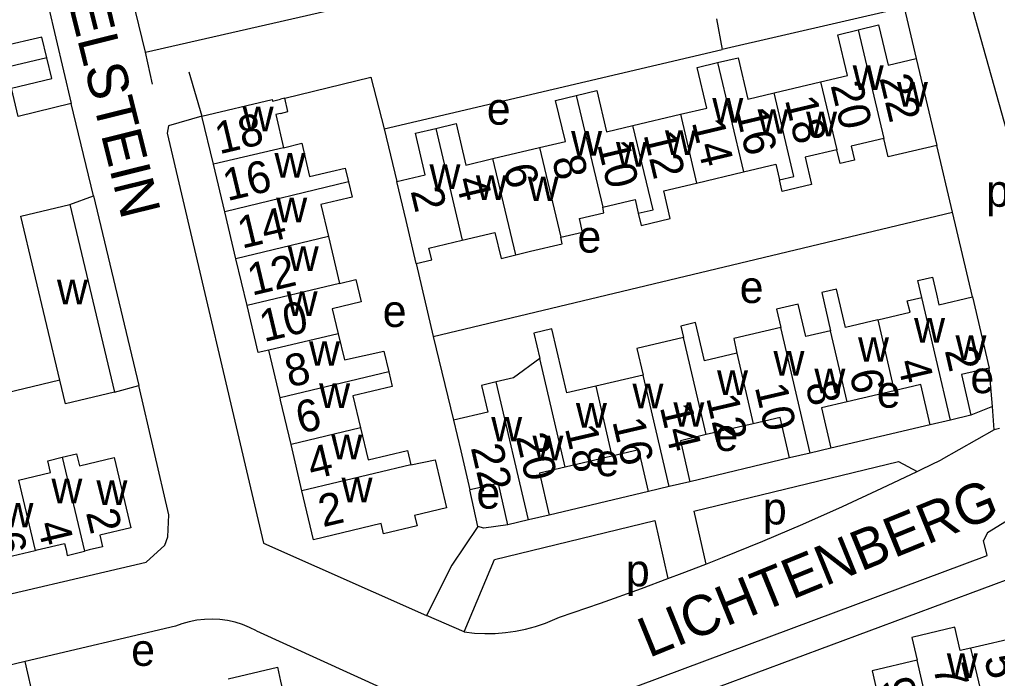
# Model space of a CAD drawing. Extents: x 157646 to 159241, y 379213 to 381217.
# Drawn here: x 158967.4 to 159089.5, y 380734 to 380816.2 of the extents above; entities that cross this region are included whole.
import ezdxf

# ---------------------------------------------------------------- set-up
doc = ezdxf.new("R2010")
doc.units = 0
for name, color, linetype in [('BLT_Basislijn', 7, 'Continuous'), ('BLT_Bebouwing', 7, 'Continuous'), ('BLT_Centroide', 7, 'Continuous'), ('BLT_Huisnummer', 7, 'Continuous'), ('BLT_Huisnummer_ tussenligend', 7, 'Continuous'), ('BLT_Onderverdeling_panden', 7, 'Continuous'), ('BLT_Straatnaam', 7, 'Continuous')]:
    doc.layers.add(name, color=color, linetype=linetype)

msp = doc.modelspace()

# ---------------------------------------------------------------- linework, layer by layer
at = {"layer": 'BLT_Basislijn'}
for p, q in [((158983.11, 380812.15), (158977.53, 380835.61)), ((158983.11, 380812.15), (159034.87, 380824)), ((159077.86, 380817.75), (159079.36, 380811.37)), ((159054.42, 380816.35), (159055.16, 380812.49)), ((158984, 380808.18), (158983.11, 380812.15)), ((159012.95, 380802.61), (159055.16, 380812.49)), ((158973.83, 380805.75), (158967.23, 380804.14)), ((158976.62, 380794.22), (158973.83, 380805.75)), ((159012.95, 380802.61), (159014.5, 380796)), ((159083.91, 380792.17), (159081.95, 380800.52)), ((158973.68, 380793.14), (158976.62, 380794.22)), ((158976.62, 380794.22), (158982.31, 380770.52)), ((159019.06, 380776.66), (159083.91, 380792.17)), ((159086.41, 380781.6), (159083.91, 380792.17)), ((159016.94, 380785.76), (159019.06, 380776.66)), ((159019.06, 380776.66), (159021.61, 380766.21)), ((159088.89, 380767.92), (159088.48, 380772.7)), ((158972.42, 380771.22), (158961.87, 380768.65)), ((158979.25, 380769.69), (158982.31, 380770.52)), ((159088.89, 380767.92), (159086.19, 380766.82)), ((159089.11, 380764.99), (159088.89, 380767.92)), ((159081.12, 380765.64), (159068.72, 380762.7)), ((159089.11, 380764.99), (159082.49, 380761.27)), ((159089.77, 380765.17), (159089.11, 380764.99)), ((159063.55, 380761.5), (159051.11, 380758.53)), ((159024.61, 380752.92), (159023.64, 380757.49)), ((159045.93, 380757.32), (159033.55, 380754.35)), ((159051.59, 380754.84), (159053.09, 380748.24)), ((159046.73, 380753.67), (159048.37, 380746.43)), ((159035.86, 380725.94), (159107.8, 380752.64)), ((159022.93, 380739.77), (159018.2, 380741.8)), ((158986.88, 380740.47), (158968.1, 380736.07)), ((158996.99, 380739.89), (159012.87, 380732.66)), ((158968.1, 380736.07), (158959.72, 380734.11)), ((158969.87, 380728.34), (158968.1, 380736.07))]:
    msp.add_line(p, q, dxfattribs=at)
for points in [[(158950.45, 380874.83), (158953.9, 380875.15), (158955.51, 380874.99), (158957.69, 380873.05), (158958.48, 380871.06), (158973.83, 380805.75)], [(159085.81, 380819.61), (159092.6, 380795.38), (159096.65, 380780.35)], [(159077.86, 380817.75), (159077.39, 380817.64), (159055.16, 380812.49)], [(158988.55, 380809.71), (158990.18, 380804.18)], [(159000.52, 380806.43), (159011.27, 380809.03), (159012.95, 380802.61)], [(158990.18, 380804.18), (158985.98, 380802.97), (158985.82, 380802.07), (158997.85, 380750.84), (159018.2, 380741.8)], [(158934.65, 380738.13), (158934.9, 380737.3), (158935.48, 380737.32), (158983.21, 380748.46), (158985.53, 380750.59), (158985.91, 380751.64), (158986.02, 380754.38), (158982.31, 380770.52)], [(159051.59, 380754.84), (159077.17, 380761.03), (159079.5, 380759.81)], [(159079.5, 380759.81), (159079.98, 380760.04), (159082.49, 380761.27)], [(159053.09, 380748.24), (159055.2, 380749.07), (159060.22, 380751.11), (159065.21, 380753.24), (159070.17, 380755.43), (159075.09, 380757.7), (159079.5, 380759.81)], [(159094.81, 380755.74), (159091.19, 380753.93), (159088.28, 380752.14), (159087.76, 380751.2)], [(159022.93, 380739.77), (159026.72, 380748.83), (159046.73, 380753.67)], [(159024.61, 380752.92), (159021.37, 380748.1), (159018.2, 380741.8)], [(159028.39, 380753.15), (159025.37, 380752.73), (159024.61, 380752.92)], [(159035.62, 380732.02), (159039.36, 380731.08), (159088.22, 380749.33), (159087.76, 380751.2)], [(159048.37, 380746.43), (159050.15, 380747.09), (159053.09, 380748.24)], [(159034.83, 380741.62), (159039.96, 380743.37), (159045.07, 380745.19), (159048.37, 380746.43)], [(158996.99, 380739.89), (158996.12, 380740.32), (158995.23, 380740.68), (158994.31, 380740.97), (158993.37, 380741.18), (158992.42, 380741.3), (158991.46, 380741.36), (158990.49, 380741.33), (158989.54, 380741.22), (158988.59, 380741.03), (158987.67, 380740.76), (158986.88, 380740.47)], [(159022.93, 380739.77), (159024.21, 380739.62), (159025.5, 380739.57), (159026.78, 380739.58), (159028.07, 380739.68), (159029.34, 380739.86), (159030.6, 380740.12), (159031.85, 380740.46), (159033.06, 380740.87), (159034.26, 380741.36), (159034.83, 380741.62)]]:
    msp.add_lwpolyline(points, dxfattribs=at)
at = {"layer": 'BLT_Bebouwing'}
for p, q in [((159079.36, 380811.37), (159081.95, 380800.52)), ((159061.64, 380807.09), (159067.44, 380808.47)), ((159000.52, 380806.43), (159000, 380806.3)), ((158999.99, 380804.52), (158999.4, 380804.38)), ((158999.4, 380804.38), (159000.38, 380800.24)), ((159043.98, 380802.99), (159049.93, 380804.41)), ((159026.52, 380798.87), (159032.32, 380800.25)), ((158993.03, 380792.21), (158991.61, 380798.16)), ((159051.93, 380795.82), (159057.81, 380797.22)), ((158973.68, 380793.14), (158979.25, 380769.69)), ((158994.42, 380786.37), (158993.03, 380792.21)), ((158995.81, 380780.54), (158994.42, 380786.37)), ((159086.41, 380781.6), (159088.48, 380772.7)), ((159007.18, 380777), (159007.96, 380773.73)), ((158999.93, 380769.02), (158998.52, 380774.94)), ((159045.26, 380771.82), (159039.35, 380770.45)), ((159076.63, 380769.89), (159070.75, 380768.52)), ((159000, 380768.7), (158999.93, 380769.02)), ((159001.3, 380763.19), (159000, 380768.7)), ((159059.01, 380765.76), (159053.14, 380764.4)), ((159083.65, 380766.23), (159081.12, 380765.64)), ((159086.19, 380766.82), (159083.65, 380766.23)), ((159002.67, 380757.39), (159001.3, 380763.19)), ((159066.13, 380762.1), (159063.55, 380761.5)), ((159068.72, 380762.7), (159066.13, 380762.1)), ((159041.38, 380761.72), (159035.53, 380760.36)), ((159051.11, 380758.53), (159048.52, 380757.93)), ((159048.52, 380757.93), (159045.93, 380757.32)), ((159030.97, 380753.75), (159028.39, 380753.15)), ((159033.55, 380754.35), (159030.97, 380753.75)), ((159092.8, 380739.29), (159086.2, 380737.74))]:
    msp.add_line(p, q, dxfattribs=at)
for points in [[(158970.81, 380811.46), (158970.2, 380814.05), (158965.13, 380812.86), (158964.36, 380816.13)], [(159067.44, 380808.47), (159070.79, 380809.27), (159069.58, 380814.35), (159072.12, 380814.96)], [(159072.12, 380814.96), (159074.67, 380815.56), (159075.86, 380810.54), (159079.36, 380811.37)], [(158967.23, 380804.14), (158966.4, 380807.68), (158971.42, 380808.86), (158970.81, 380811.46)], [(159049.93, 380804.41), (159053.22, 380805.19), (159052.01, 380810.25), (159054.57, 380810.86)], [(159054.57, 380810.86), (159057.13, 380811.47), (159058.36, 380806.31), (159061.64, 380807.09)], [(159036.91, 380806.75), (159039.48, 380807.36), (159040.7, 380802.21), (159043.98, 380802.99)], [(158990.18, 380804.18), (158998.94, 380806.26), (158998.99, 380806.06), (159000, 380806.3)], [(158999.99, 380804.52), (159000.91, 380804.74), (159000.52, 380806.43)], [(159032.32, 380800.25), (159035.56, 380801.02), (159034.34, 380806.14), (159036.91, 380806.75)], [(158991.61, 380798.16), (158990.18, 380804.18)], [(159014.5, 380796), (159018.07, 380796.85), (159016.83, 380802.05), (159019.37, 380802.65)], [(159019.37, 380802.65), (159021.91, 380803.25), (159023.14, 380798.06), (159026.52, 380798.87)], [(159075.34, 380801.38), (159071.26, 380800.41), (159071.67, 380798.69), (159069.87, 380798.27), (159069.47, 380799.99)], [(159081.95, 380800.52), (159075.89, 380799.08), (159075.34, 380801.38)], [(159000.38, 380800.24), (159002.63, 380800.79), (159003.61, 380796.65), (159006.27, 380797.28), (159008.05, 380797.7), (159008.46, 380795.96)], [(159069.47, 380799.99), (159065.49, 380799.04), (159066.3, 380795.65), (159062.64, 380794.78), (159062.3, 380796.23)], [(159057.81, 380797.22), (159061.83, 380798.17), (159062.3, 380796.23)], [(159008.46, 380795.96), (159008.92, 380794.06), (159007.13, 380793.64), (159005.02, 380793.14), (159005.97, 380789.15)], [(159016.94, 380785.76), (159015.66, 380791.14), (159014.5, 380796)], [(159044.67, 380792.05), (159045.03, 380790.54), (159048.66, 380791.4), (159047.84, 380794.85), (159051.93, 380795.82)], [(159040.23, 380792.82), (159044.26, 380793.78), (159044.67, 380792.05)], [(158972.42, 380771.22), (158967.56, 380791.68), (158973.68, 380793.14)], [(159034.99, 380789.05), (159037.72, 380789.7), (159037.32, 380791.4), (159040.38, 380792.12), (159040.23, 380792.82)], [(159005.97, 380789.15), (159007.37, 380783.27)], [(159022.69, 380788.68), (159026.77, 380789.66), (159027.54, 380786.42), (159029.38, 380786.86)], [(159029.38, 380786.86), (159031.22, 380787.3), (159035.18, 380788.24), (159034.99, 380789.05)], [(159016.94, 380785.76), (159018.88, 380786.22), (159018.53, 380787.69), (159022.69, 380788.68)], [(159080.09, 380781.55), (159079.56, 380783.65), (159081.4, 380784.08), (159081.89, 380781.96), (159082.2, 380780.62), (159086.41, 380781.6)], [(159007.37, 380783.27), (159009.41, 380783.78), (159010.07, 380780.99), (159006.44, 380780.12), (159007.18, 380777)], [(159074.57, 380778.74), (159070.55, 380777.8), (159069.44, 380782.58), (159067.58, 380782.15), (159068.69, 380777.36)], [(159074.57, 380778.74), (159078.6, 380779.68), (159078.26, 380781.12), (159080.09, 380781.55)], [(158998.52, 380774.94), (158997.21, 380774.65), (158995.81, 380780.54)], [(159068.69, 380777.36), (159065.59, 380776.65), (159064.65, 380780.71), (159061.92, 380780.08), (159062.46, 380777.77)], [(159056.97, 380774.57), (159052.92, 380773.63), (159051.81, 380778.4), (159049.99, 380777.97), (159050.33, 380776.52)], [(159039.35, 380770.45), (159035.73, 380769.61), (159033.88, 380777.6), (159031.64, 380777.08), (159032.38, 380773.93)], [(159062.46, 380777.77), (159056.58, 380776.4), (159056.97, 380774.57)], [(159050.33, 380776.52), (159044.48, 380775.15), (159045.26, 380771.82)], [(159007.96, 380773.73), (159012.91, 380774.81), (159013.52, 380772.25)], [(159032.38, 380773.93), (159029.08, 380771.48), (159026.93, 380770.98)], [(159013.52, 380772.25), (159013.95, 380770.42), (159009.03, 380769.25), (159009.98, 380765.26)], [(159088.48, 380772.7), (159085.01, 380771.9), (159086.19, 380766.82)], [(158979.25, 380769.69), (158973.13, 380768.24), (158972.42, 380771.22)], [(159026.93, 380770.98), (159025.08, 380770.55), (159025.86, 380767.2), (159021.61, 380766.21)], [(159081.12, 380765.64), (159079.95, 380770.66), (159076.63, 380769.89)], [(159070.75, 380768.52), (159067.54, 380767.77), (159068.72, 380762.7)], [(159021.61, 380766.21), (159022.51, 380762.36), (159023.64, 380757.49)], [(159063.55, 380761.5), (159062.38, 380766.54), (159059.01, 380765.76)], [(159009.98, 380765.26), (159010.93, 380761.27), (159015.83, 380762.44), (159016.26, 380760.63)], [(159053.14, 380764.4), (159049.92, 380763.65), (159051.11, 380758.53)], [(158972.73, 380761.57), (158974.53, 380761.99), (158974.88, 380760.5), (158979.21, 380761.53), (158981.28, 380752.78), (158977.42, 380751.86), (158977.77, 380750.4), (158976.09, 380750), (158975.5, 380749.86)], [(159045.93, 380757.32), (159044.73, 380762.49), (159041.38, 380761.72)], [(158967.26, 380758.72), (158971.28, 380759.67), (158970.93, 380761.14), (158972.73, 380761.57)], [(159016.26, 380760.63), (159019.3, 380761.25), (159020.73, 380755.27), (159016.74, 380754.32), (159017.05, 380753.02), (159012.86, 380752.02), (159012.56, 380753.29), (159004.12, 380751.28), (159002.67, 380757.39)], [(159035.53, 380760.36), (159032.33, 380759.61), (159033.55, 380754.35)], [(159028.39, 380753.15), (159027.19, 380758.31), (159023.64, 380757.49)], [(158963.95, 380747.07), (158966.16, 380747.58), (158965.8, 380749.09), (158969.34, 380749.94)], [(158969.34, 380749.94), (158969.58, 380750), (158973, 380750.81), (158973.2, 380750), (158973.35, 380749.33), (158975.5, 380749.86)], [(159086.2, 380737.74), (159084.87, 380737.43), (159084.18, 380740.35), (159078.81, 380739.08), (159079.49, 380736.22)], [(158993.46, 380733.9), (158999.6, 380735.35), (159000, 380733.62), (159000.93, 380729.7), (159007.93, 380731.35), (159009.55, 380724.49), (159002.57, 380722.84), (159001.67, 380726.68), (159000, 380726.29), (158997.3, 380725.65), (158998.46, 380720.75), (158996.66, 380720.33)], [(159079.49, 380736.22), (159073.88, 380734.89), (159074.56, 380731.99)]]:
    msp.add_lwpolyline(points, dxfattribs=at)
at = {"layer": 'BLT_Onderverdeling_panden'}
for p, q in [((159072.12, 380814.96), (159075.34, 380801.38)), ((158970.81, 380811.46), (158956.95, 380808.19)), ((159054.57, 380810.86), (159057.81, 380797.22)), ((159067.44, 380808.47), (159069.47, 380799.99)), ((159036.91, 380806.75), (159040.23, 380792.82)), ((159019.37, 380802.65), (159022.69, 380788.68)), ((159000.38, 380800.24), (158991.61, 380798.16)), ((159032.32, 380800.25), (159034.99, 380789.05)), ((159029.38, 380786.86), (159026.52, 380798.87)), ((159008.46, 380795.96), (158993.03, 380792.21)), ((159005.97, 380789.15), (158994.42, 380786.37)), ((159007.37, 380783.27), (158995.81, 380780.54)), ((159083.65, 380766.23), (159080.09, 380781.55)), ((159074.57, 380778.74), (159076.63, 380769.89)), ((159007.18, 380777), (158998.52, 380774.94)), ((159066.13, 380762.1), (159062.46, 380777.77)), ((159070.75, 380768.52), (159068.69, 380777.36)), ((159053.14, 380764.4), (159050.33, 380776.52)), ((159056.97, 380774.57), (159059.01, 380765.76)), ((159035.53, 380760.36), (159032.38, 380773.93)), ((159013.52, 380772.25), (158999.93, 380769.02)), ((159048.52, 380757.93), (159045.26, 380771.82)), ((159030.97, 380753.75), (159026.93, 380770.98)), ((159039.35, 380770.45), (159041.38, 380761.72)), ((159009.98, 380765.26), (159001.3, 380763.19)), ((158972.73, 380761.57), (158975.5, 380749.86)), ((159016.26, 380760.63), (159002.67, 380757.39)), ((158967.26, 380758.72), (158969.34, 380749.94)), ((159087.56, 380731.95), (159086.2, 380737.74)), ((159081.54, 380727.5), (159079.49, 380736.22))]:
    msp.add_line(p, q, dxfattribs=at)
for points in [[(159062.3, 380796.23), (159064.11, 380796.66), (159061.64, 380807.09)], [(159049.93, 380804.41), (159051.93, 380795.82)], [(159044.67, 380792.05), (159046.52, 380792.49), (159043.98, 380802.99)]]:
    msp.add_lwpolyline(points, dxfattribs=at)

# ---------------------------------------------------------------- texts
at = {"layer": 'BLT_Centroide'}
for s, p in [('w', (159071.44, 380807.44)), ('w', (159076.97, 380805.38)), ('e', (159025.75, 380803.11)), ('w', (159053.91, 380803.36)), ('w', (158995.26, 380802.28)), ('w', (159059.56, 380801.97)), ('w', (159065.62, 380801.67)), ('w', (159036.28, 380799.23)), ('w', (159048, 380799.33)), ('w', (159041.88, 380797.86)), ('w', (158999.23, 380796.5)), ('w', (159018.59, 380795.09)), ('w', (159024.38, 380793.72)), ('w', (159030.86, 380793.56)), ('p', (159088.1, 380792.86)), ('w', (158999.45, 380790.91)), ('e', (159037.07, 380787.14)), ('w', (159000.89, 380784.84)), ('e', (159057.33, 380780.84)), ('w', (158972.07, 380780.69)), ('w', (159000.75, 380779.22)), ('e', (159012.75, 380777.85)), ('w', (159079.11, 380775.89)), ('w', (159084.28, 380773.73)), ('w', (159003.55, 380773)), ('w', (159072.11, 380773.5)), ('w', (159061.55, 380771.77)), ('w', (159054.5, 380769.36)), ('w', (159066.66, 380769.56)), ('e', (159086.14, 380769.58)), ('w', (159004.81, 380767.72)), ('w', (159043.94, 380767.7)), ('e', (159074.44, 380767.77)), ('w', (159036.88, 380765.27)), ('w', (159049.05, 380765.38)), ('w', (159026.3, 380763.55)), ('e', (159054.18, 380762.37)), ('w', (159006.33, 380761.31)), ('w', (159031.45, 380761.2)), ('e', (159039.32, 380759.22)), ('w', (158971.38, 380755.84)), ('w', (158977, 380755.61)), ('w', (159007.61, 380755.94)), ('e', (159024.46, 380755.16)), ('w', (158965.27, 380752.81)), ('p', (159060.23, 380753.19)), ('p', (159043.12, 380745.46)), ('e', (158981.34, 380735.53)), ('w', (159083.19, 380734.02))]:
    msp.add_text(s, height=4, dxfattribs=at).set_placement(p)
at = {"layer": 'BLT_Huisnummer'}
for s, rotation, p in [('22', 283.3954, (159074.75, 380808.96)), ('18', 283.3954, (159062.96, 380806.23)), ('18', 13.3907, (158992.34, 380799.4)), ('14', 283.3954, (159051.33, 380803.43)), ('10', 283.3954, (159039.52, 380800.68)), ('6', 283.3954, (159027.78, 380797.78)), ('2', 283.3954, (159016.21, 380794.84)), ('14', 13.3907, (158995.17, 380787.61)), ('10', 13.3907, (158997.91, 380775.95)), ('2', 283.0817, (159082.92, 380774.93)), ('6', 283.0817, (159071, 380772.14)), ('10', 283.0817, (159059.2, 380770.36)), ('6', 13.3907, (159002.45, 380764.49)), ('14', 283.0817, (159047.34, 380767.85)), ('18', 283.0817, (159035.48, 380765.21)), ('22', 283.0817, (159023.73, 380762.79)), ('2', 13.3907, (159005.27, 380752.83)), ('2', 283.3299, (158975.67, 380754.68)), ('6', 283.3299, (158963.86, 380751.83)), ('5', 283.2786, (159087.83, 380736.53)), ('9', 283.2802, (159074.96, 380733.61))]:
    msp.add_text(s, height=4, rotation=rotation, dxfattribs=at).set_placement(p)
at = {"layer": 'BLT_Huisnummer_ tussenligend'}
for s, rotation, p in [('20', 283.3954, (159068.66, 380808.04)), ('16', 283.3954, (159056.8, 380804.8)), ('12', 283.3954, (159045.3, 380801.88)), ('16', 13.3907, (158993.34, 380793.55)), ('8', 283.3954, (159033.86, 380798.84)), ('4', 283.3954, (159021.83, 380796.23)), ('12', 13.3907, (158996.41, 380781.74)), ('8', 13.3907, (159001.09, 380770.27)), ('4', 283.0817, (159076.99, 380773.46)), ('8', 283.0817, (159065.52, 380770.65)), ('12', 283.0817, (159053.12, 380769.01)), ('16', 283.0817, (159041.41, 380766.07)), ('20', 283.0817, (159029.34, 380764.16)), ('4', 13.3907, (159003.89, 380758.76)), ('4', 283.3299, (158969.59, 380753.21)), ('7', 283.2786, (159081.46, 380735.36))]:
    msp.add_text(s, height=4, rotation=rotation, dxfattribs=at).set_placement(p)
at = {"layer": 'BLT_Straatnaam'}
for s, height, rotation, p in [('HARTELSTEIN', 5, 283.9525, (158969.12, 380835.8)), ('LICHTENBERG', 4.9999, 22.1483, (159045.98, 380736.49))]:
    msp.add_text(s, height=height, rotation=rotation, dxfattribs=at).set_placement(p)

doc.saveas('drawing.dxf')
